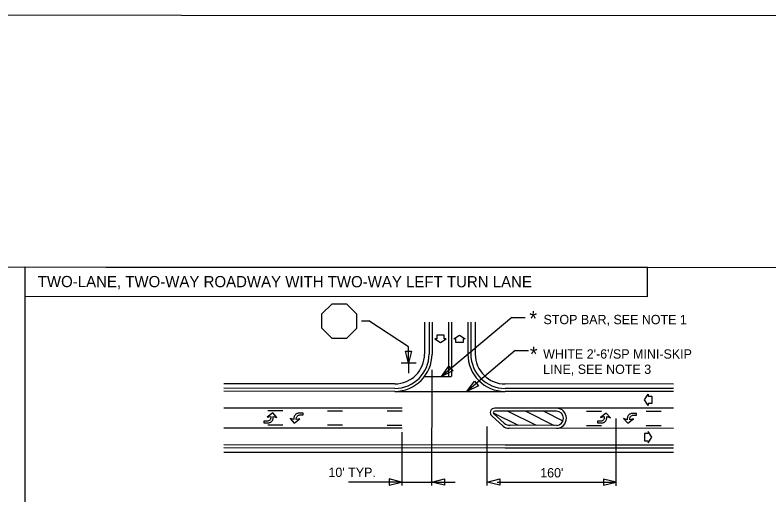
# Model space of a CAD drawing. Extents: x 50667 to 52386, y 46650 to 50479.
# Drawn here: x 51455 to 52036, y 47500 to 47871 of the extents above; entities that cross this region are included whole.
import ezdxf

# ---------------------------------------------------------------- set-up
doc = ezdxf.new("R2010")
doc.units = 0
for name, color, linetype in [('Default', 7, 'Continuous'), ('DEV TUBULAR MARKER SECTIONAL VIEW CELL', 7, 'Continuous'), ('Exist Building', 7, 'Continuous'), ('Exist Guardrail Text', 7, 'Continuous'), ('Exist Hydro Spring Text', 7, 'Continuous'), ('Exist Right of Way Monument Text', 7, 'Continuous'), ('Gray Area Fill Shapes', 7, 'Continuous'), ('Prop EOT Dash', 7, 'Continuous')]:
    doc.layers.add(name, color=color, linetype=linetype)

msp = doc.modelspace()

# ---------------------------------------------------------------- linework, layer by layer
at = {"layer": 'Default'}
for p, q in [((51462.45, 47676.12), (51462.09, 46906.44)), ((51691.54, 47639.97), (51699.35, 47647.78)), ((51699.35, 47647.78), (51710.42, 47647.77)), ((51710.42, 47647.77), (51718.23, 47639.96)), ((51691.53, 47628.9), (51691.54, 47639.97)), ((51718.23, 47639.96), (51718.22, 47628.89)), ((51721.92, 47634.59), (51727.67, 47634.59)), ((51758.31, 47614.65), (51727.67, 47634.59)), ((51770.7, 47633.63), (51770.69, 47609.01)), ((51774.15, 47633.62), (51774.14, 47609.01)), ((51776.45, 47633.62), (51776.44, 47609.01)), ((51837.87, 47637.2), (51783.75, 47591.75)), ((51789.1, 47633.62), (51789.08, 47591.75)), ((51791.4, 47633.62), (51791.38, 47591.75)), ((51804.05, 47633.61), (51804.04, 47608.99)), ((51806.35, 47633.61), (51806.34, 47608.99)), ((51809.8, 47633.61), (51809.79, 47608.99)), ((51837.87, 47637.2), (51848.25, 47637.19)), ((51699.34, 47621.09), (51691.53, 47628.9)), ((51718.22, 47628.89), (51710.41, 47621.08)), ((51710.41, 47621.08), (51699.34, 47621.09)), ((51758.3, 47601.9), (51758.31, 47614.65)), ((51840.57, 47611.68), (51803.35, 47580.24)), ((51840.57, 47611.68), (51850.95, 47611.68)), ((51776.4, 47507.53), (51776.44, 47596.77)), ((51770.69, 47591.76), (51791.1, 47591.75)), ((51747.68, 47586.02), (51615.91, 47586.08)), ((51962.78, 47585.92), (51832.78, 47585.98)), ((51747.68, 47582.57), (51615.91, 47582.63)), ((51747.68, 47580.27), (51615.91, 47580.33)), ((51805.01, 47581.64), (51803.35, 47580.24)), ((51962.78, 47582.47), (51832.78, 47582.53)), ((51962.77, 47580.17), (51832.78, 47580.23)), ((51753.42, 47567.33), (51615.91, 47567.39)), ((51823.7, 47563.65), (51842.85, 47554.06)), ((51824.07, 47562.99), (51832.15, 47555.81)), ((51962.77, 47567.23), (51824.83, 47567.3)), ((51872.4, 47564.98), (51824.83, 47565)), ((51834.8, 47564.99), (51856.65, 47554.06)), ((51848.68, 47564.99), (51870.53, 47554.05)), ((51862.56, 47564.98), (51877.44, 47557.53)), ((51822.54, 47561.27), (51831.28, 47553.51)), ((51918.37, 47507.47), (51918.39, 47559.31)), ((51753.42, 47551.81), (51615.9, 47551.87)), ((51819.05, 47507.51), (51819.07, 47553.22)), ((51962.76, 47551.71), (51835.86, 47551.77)), ((51872.39, 47554.05), (51836.73, 47554.07)), ((51753.4, 47507.54), (51753.42, 47548.75)), ((51832.76, 47538.83), (51615.89, 47538.93)), ((51962.76, 47538.77), (51832.76, 47538.83)), ((51832.76, 47536.53), (51615.89, 47536.63)), ((51832.76, 47533.08), (51615.89, 47533.18)), ((51962.75, 47536.47), (51832.76, 47536.53)), ((51962.75, 47533.02), (51832.76, 47533.08)), ((51752.89, 47510.3), (51712.02, 47510.32)), ((51750.72, 47510.3), (51752.89, 47510.3)), ((51753.4, 47510.3), (51776.4, 47510.29)), ((51778.57, 47510.29), (51776.4, 47510.29)), ((51776.4, 47510.29), (51794.35, 47510.28)), ((51821.22, 47510.27), (51819.05, 47510.27)), ((51826.76, 47510.27), (51918.37, 47510.23)), ((51916.2, 47510.23), (51918.37, 47510.23))]:
    msp.add_line(p, q, dxfattribs=at)
for points in [[(51661.28, 47565.13), (51649.78, 47565.14)], [(51707.28, 47565.11), (51695.78, 47565.11)], [(51753.28, 47565.09), (51741.78, 47565.09)], [(51895.55, 47565.02), (51907.05, 47565.02)], [(51941.55, 47565), (51953.05, 47565)], [(51661.28, 47554.09), (51649.78, 47554.1)], [(51707.27, 47554.07), (51695.78, 47554.07)], [(51753.27, 47554.05), (51741.77, 47554.05)], [(51895.55, 47553.98), (51907.05, 47553.98)], [(51941.55, 47553.96), (51953.05, 47553.96)]]:
    msp.add_lwpolyline(points, dxfattribs=at)
for centre, radius, start, end in [((51747.69, 47609.03), 28.75, 269.97341, 359.97341), ((51747.69, 47609.03), 26.45, 269.97341, 359.97341), ((51747.69, 47609.03), 23, 269.97341, 359.97341), ((51832.79, 47608.99), 28.75, 179.97341, 269.97341), ((51832.79, 47608.99), 26.45, 179.97341, 269.97341), ((51832.79, 47608.99), 23, 179.97341, 269.97341), ((51824.83, 47563.85), 3.45, 89.97341, 228.38768), ((51824.83, 47563.85), 1.15, 89.97341, 228.38768), ((51872.34, 47559.51), 7.76, 270.39584, 89.55098), ((51872.35, 47559.51), 5.46, 270.39584, 89.55098), ((51835.86, 47558.67), 6.9, 228.38768, 269.97341), ((51836.73, 47560.97), 6.9, 228.38768, 269.97341)]:
    msp.add_arc(centre, radius, start, end, dxfattribs=at)
at = {"layer": 'DEV TUBULAR MARKER SECTIONAL VIEW CELL'}
for points in [[(50879.23, 46906.71), (50879.58, 47676.39), (52169.91, 47675.79), (52169.55, 46906.11)], [(51462.44, 47653.59), (51942.74, 47653.37), (51942.75, 47675.89), (51462.45, 47676.12)]]:
    msp.add_lwpolyline(points, close=True, dxfattribs=at)
at = {"layer": 'Exist Building'}
for points in [[(51646.83, 47557.27), (51646.83, 47556.02), (51650.05, 47556.02), (51650.64, 47556.05), (51651.09, 47556.13), (51651.58, 47556.29), (51652, 47556.5), (51652.31, 47556.72), (51652.72, 47557.07), (51653, 47557.39), (51653.29, 47557.76), (51653.58, 47558.25), (51653.74, 47558.64), (51653.9, 47559.17), (51654, 47559.9), (51654, 47560.9), (51656.8, 47560.07), (51653.58, 47563.6), (51649.22, 47560.28), (51652.02, 47560.9), (51652.02, 47560.07), (51652, 47559.6), (51651.88, 47559.17), (51651.72, 47558.84), (51651.47, 47558.41), (51651.23, 47558.11), (51650.82, 47557.78), (51650.35, 47557.54), (51649.88, 47557.37), (51649.22, 47557.27)], [(51676.96, 47562.13), (51676.96, 47563.37), (51673.75, 47563.37), (51673.15, 47563.34), (51672.7, 47563.26), (51672.21, 47563.11), (51671.8, 47562.89), (51671.48, 47562.68), (51671.07, 47562.32), (51670.8, 47562.01), (51670.5, 47561.64), (51670.21, 47561.15), (51670.05, 47560.75), (51669.89, 47560.22), (51669.79, 47559.5), (51669.79, 47558.5), (51666.99, 47559.33), (51670.21, 47555.8), (51674.57, 47559.12), (51671.77, 47558.49), (51671.77, 47559.33), (51671.8, 47559.79), (51671.91, 47560.22), (51672.07, 47560.56), (51672.33, 47560.99), (51672.56, 47561.28), (51672.97, 47561.61), (51673.44, 47561.85), (51673.92, 47562.03), (51674.57, 47562.13)], [(51904.06, 47557.15), (51904.06, 47555.9), (51907.28, 47555.9), (51907.87, 47555.93), (51908.32, 47556.01), (51908.81, 47556.17), (51909.23, 47556.38), (51909.54, 47556.6), (51909.95, 47556.95), (51910.23, 47557.27), (51910.52, 47557.64), (51910.82, 47558.13), (51910.97, 47558.52), (51911.13, 47559.05), (51911.23, 47559.78), (51911.23, 47560.78), (51914.03, 47559.95), (51910.81, 47563.48), (51906.45, 47560.16), (51909.25, 47560.78), (51909.25, 47559.95), (51909.23, 47559.48), (51909.11, 47559.05), (51908.95, 47558.72), (51908.7, 47558.29), (51908.46, 47557.99), (51908.05, 47557.66), (51907.58, 47557.42), (51907.11, 47557.25), (51906.45, 47557.15)], [(51934.19, 47562.01), (51934.19, 47563.25), (51930.98, 47563.25), (51930.38, 47563.22), (51929.93, 47563.14), (51929.44, 47562.99), (51929.03, 47562.77), (51928.71, 47562.56), (51928.3, 47562.2), (51928.03, 47561.89), (51927.73, 47561.52), (51927.44, 47561.03), (51927.28, 47560.63), (51927.12, 47560.1), (51927.03, 47559.38), (51927.03, 47558.38), (51924.23, 47559.21), (51927.44, 47555.68), (51931.8, 47559), (51929, 47558.38), (51929, 47559.21), (51929.03, 47559.67), (51929.15, 47560.1), (51929.3, 47560.44), (51929.56, 47560.87), (51929.79, 47561.16), (51930.2, 47561.5), (51930.68, 47561.73), (51931.15, 47561.91), (51931.81, 47562.01)]]:
    msp.add_lwpolyline(points, close=True, dxfattribs=at)
at = {"layer": 'Exist Guardrail Text'}
for p, q in [((51764.17, 47601.9), (51752.52, 47601.9)), ((51758.3, 47601.9), (51758.3, 47594.35))]:
    msp.add_line(p, q, dxfattribs=at)
at = {"layer": 'Exist Hydro Spring Text'}
msp.add_line((51747.67, 47580.28), (51832.77, 47580.24), dxfattribs=at)
at = {"layer": 'Exist Right of Way Monument Text'}
msp.add_lwpolyline([(52335.61, 47869.9), (50830.4, 47870.6), (50829.91, 46815.38), (52335.12, 46814.68)], close=True, dxfattribs=at)
at = {"layer": 'Gray Area Fill Shapes'}
for points in [[(51780.03, 47623.69), (51780.03, 47620.82), (51778.6, 47620.82), (51782.95, 47617.94), (51787.22, 47620.81), (51785.78, 47620.81), (51785.78, 47623.69)], [(51794.72, 47617.94), (51794.73, 47620.81), (51793.29, 47620.81), (51797.65, 47623.68), (51801.91, 47620.81), (51800.48, 47620.81), (51800.47, 47617.93)], [(51946.06, 47570.88), (51943.19, 47570.88), (51943.19, 47569.45), (51940.32, 47573.81), (51943.19, 47578.07), (51943.19, 47576.63), (51946.07, 47576.63)], [(51940.3, 47542.1), (51943.18, 47542.1), (51943.18, 47540.67), (51946.05, 47545.03), (51943.18, 47549.29), (51943.18, 47547.85), (51940.3, 47547.85)]]:
    msp.add_lwpolyline(points, close=True, dxfattribs=at)
at = {"layer": 'Prop EOT Dash'}
for points in [[(51760.68, 47611.39), (51758.3, 47601.9), (51755.93, 47611.39)], [(51760.68, 47611.39), (51758.3, 47601.9), (51755.93, 47611.39)], [(51792.54, 47596.04), (51783.75, 47591.75), (51789.49, 47599.67)], [(51792.54, 47596.04), (51783.75, 47591.75), (51789.49, 47599.67)], [(51812.21, 47584.6), (51803.35, 47580.24), (51809.12, 47588.26)], [(51812.21, 47584.6), (51803.35, 47580.24), (51809.12, 47588.26)], [(51743.3, 47507.91), (51752.89, 47510.3), (51743.3, 47512.7)], [(51743.3, 47507.91), (51752.89, 47510.3), (51743.3, 47512.7)], [(51785.98, 47507.89), (51776.4, 47510.29), (51785.98, 47512.68)], [(51785.98, 47507.89), (51776.4, 47510.29), (51785.98, 47512.68)], [(51828.63, 47507.87), (51819.05, 47510.27), (51828.64, 47512.66)], [(51828.63, 47507.87), (51819.05, 47510.27), (51828.64, 47512.66)], [(51908.79, 47507.83), (51918.37, 47510.23), (51908.79, 47512.63)], [(51908.79, 47507.83), (51918.37, 47510.23), (51908.79, 47512.63)]]:
    msp.add_lwpolyline(points, close=True, dxfattribs=at)

# ---------------------------------------------------------------- texts
at = {"layer": 'Default'}
for s, height, p in [('TWO-LANE, TWO-WAY ROADWAY WITH TWO-WAY LEFT TURN LANE', 8.652, (51472.33, 47660.68)), ('*', 11.5, (51851.49, 47630.7)), ('STOP BAR, SEE NOTE 1', 7.1874, (51862.41, 47632.12)), ('*', 11.5, (51851.86, 47603.26)), ("WHITE 2'-6'/SP MINI-SKIP", 7.1874, (51862.12, 47605.55)), ('LINE, SEE NOTE 3', 7.1874, (51862.11, 47593.76)), ("10' TYP.", 7.187, (51696.54, 47514.21)), ("160'", 7.187, (51859.89, 47513.86))]:
    msp.add_text(s, height=height, rotation=359.97341, dxfattribs=at).set_placement(p)

doc.saveas('drawing.dxf')
